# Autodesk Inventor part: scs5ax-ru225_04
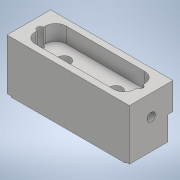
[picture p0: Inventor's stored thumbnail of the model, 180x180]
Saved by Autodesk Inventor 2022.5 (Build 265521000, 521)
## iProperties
Part Number: scs5ax-ru225_04
Material: 一般
Document SubType Name: Modeling
Designer: ImaoCorp
Density: 1 g/cm^3
Appearance: 既定
Author: ImaoCorp
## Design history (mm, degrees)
feature "scs5ax-ru225_04"
node "ソリッド1"
